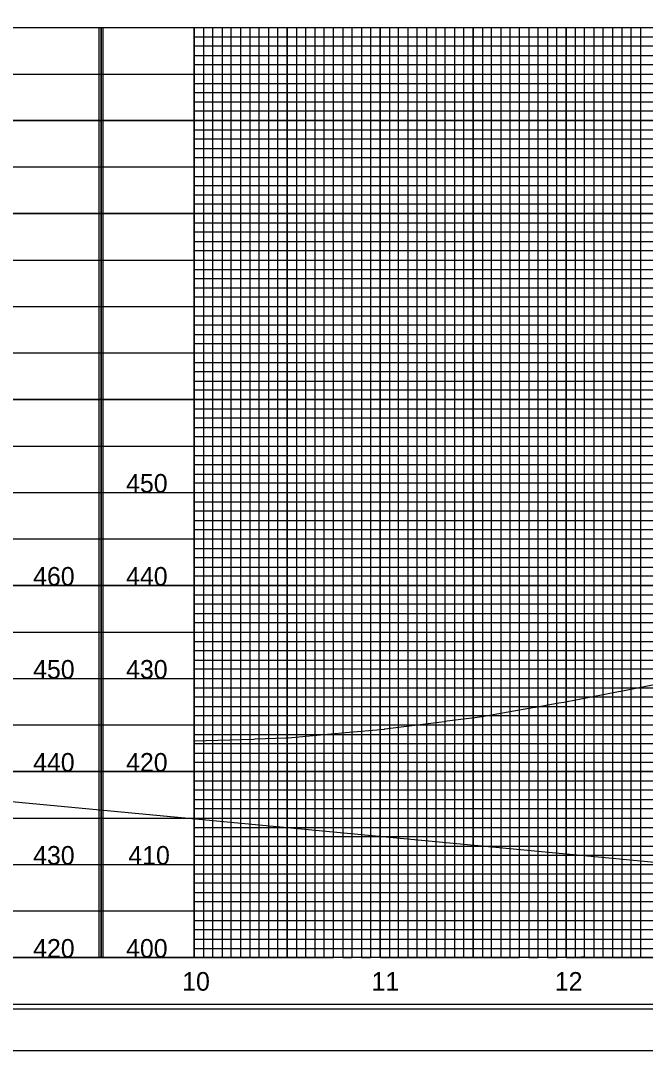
# Model space of a CAD drawing. Extents: x 571503 to 593215, y -77195 to -51828.
# Drawn here: x 586483 to 586818, y -53731 to -53168 of the extents above; entities that cross this region are included whole.
import ezdxf

# ---------------------------------------------------------------- set-up
doc = ezdxf.new("R2010")
doc.units = 0
for name, color, linetype in [('Default', 7, 'Continuous'), ('Exist Vertical Profile Ground Line', 7, 'Continuous'), ('Exist Vertical Profile Horizontal Axis Label Major', 7, 'Continuous'), ('Exist Vertical Profile Vertical Axis Label', 7, 'Continuous'), ('Prop PFL Text', 7, 'Continuous'), ('Prop VPI Label', 7, 'Continuous'), ('Sheet Clip Boundary CELL', 7, 'Continuous'), ('Sheet DOT Grid CELL', 7, 'Continuous'), ('Sheet Plot Border Inside CELL', 7, 'Continuous'), ('Sheet Plot Border Outside CELL', 7, 'Continuous'), ('Sheet Profile CELL', 7, 'Continuous'), ('Sheet Profile Grid Major CELL', 7, 'Continuous'), ('Sheet Profile Grid Middle CELL', 7, 'Continuous'), ('Sheet Profile Grid Minor CELL', 7, 'Continuous')]:
    doc.layers.add(name, color=color, linetype=linetype)

msp = doc.modelspace()

# ---------------------------------------------------------------- linework, layer by layer
at = {"layer": 'Default'}
msp.add_line((586525.93, -53671.12), (586575.93, -53671.12), dxfattribs=at)
at = {"layer": 'Exist Vertical Profile Ground Line'}
msp.add_lwpolyline([(586575.93, -53554.59), (586607.92, -53553.6), (586608.69, -53553.54), (586625.29, -53553), (586626.54, -53552.88), (586657.4, -53550.12), (586678.4, -53548.25), (586678.53, -53548.15), (586678.75, -53548.12), (586707.49, -53544.53), (586710.59, -53544.1), (586712.03, -53543.89), (586725.28, -53542.22), (586726.9, -53542.01), (586730.68, -53541.45), (586759.03, -53536.49), (586759.52, -53536.4), (586772.13, -53534.19), (586774.78, -53533.73), (586804.19, -53528.05), (586805.4, -53527.81), (586825.12, -53523.99)], dxfattribs=at)
at = {"layer": 'Prop PFL Text'}
msp.add_line((571620.66, -52186.29), (592499.52, -54154.87), dxfattribs=at)
at = {"layer": 'Prop VPI Label'}
for p, q in [((586524.93, -53671.12), (586524.93, -53171.12)), ((586526.93, -53671.12), (586526.93, -53171.12))]:
    msp.add_line(p, q, dxfattribs=at)
at = {"layer": 'Sheet Clip Boundary CELL'}
msp.add_lwpolyline([(585975.93, -53171.12), (587375.93, -53171.12), (587375.93, -53671.12), (585975.93, -53671.12)], close=True, dxfattribs=at)
at = {"layer": 'Sheet DOT Grid CELL'}
for p, q in [((585925.93, -53171.12), (587425.82, -53171.12)), ((586525.93, -53671.12), (586525.93, -53171.12)), ((586525.93, -53171.12), (586525.93, -53671.12)), ((586575.93, -53671.12), (586575.93, -53171.12)), ((586575.93, -53171.12), (586575.93, -53671.12)), ((586625.93, -53671.12), (586625.93, -53171.12)), ((586625.93, -53171.12), (586625.93, -53671.12)), ((586675.93, -53671.12), (586675.93, -53171.12)), ((586675.93, -53171.12), (586675.93, -53671.12)), ((586725.93, -53671.12), (586725.93, -53171.12)), ((586725.93, -53171.12), (586725.93, -53671.12)), ((586775.93, -53671.12), (586775.93, -53171.12)), ((586775.93, -53171.12), (586775.93, -53671.12)), ((585925.93, -53221.12), (587425.93, -53221.12)), ((585925.93, -53221.12), (587425.82, -53221.12)), ((585925.93, -53271.12), (587425.93, -53271.12)), ((585925.93, -53271.12), (587425.82, -53271.12)), ((585925.93, -53321.12), (587425.93, -53321.12)), ((585925.93, -53321.12), (587425.82, -53321.12)), ((585925.93, -53371.12), (587425.93, -53371.12)), ((585925.93, -53371.12), (587425.82, -53371.12)), ((585925.93, -53421.12), (587425.93, -53421.12)), ((585925.93, -53421.12), (587425.82, -53421.12)), ((585925.93, -53471.12), (587425.93, -53471.12)), ((585925.93, -53471.12), (587425.82, -53471.12)), ((585925.93, -53521.12), (587425.82, -53521.12)), ((585925.93, -53521.12), (586525.93, -53521.12)), ((585925.93, -53571.12), (587425.82, -53571.12)), ((586575.93, -53571.12), (587425.93, -53571.12)), ((585925.93, -53621.12), (587425.93, -53621.12)), ((585925.93, -53621.12), (587425.82, -53621.12))]:
    msp.add_line(p, q, dxfattribs=at)
at = {"layer": 'Sheet Plot Border Inside CELL'}
msp.add_lwpolyline([(585771.93, -53698.67), (587438.43, -53698.67), (587438.43, -52643.57), (585771.93, -52643.57)], close=True, dxfattribs=at)
at = {"layer": 'Sheet Plot Border Outside CELL'}
msp.add_lwpolyline([(585758.93, -53721.12), (587442.93, -53721.12), (587442.93, -52621.12), (585758.93, -52621.12)], close=True, dxfattribs=at)
at = {"layer": 'Sheet Profile CELL'}
for p, q in [((585925.93, -53171.12), (587425.93, -53171.12)), ((587425.93, -53671.12), (585925.93, -53671.12)), ((585925.93, -53696.12), (587425.93, -53696.12)), ((585758.93, -53721.12), (587442.93, -53721.12))]:
    msp.add_line(p, q, dxfattribs=at)
msp.add_lwpolyline([(587425.93, -52646.12), (585925.93, -52646.12), (585925.93, -53696.12), (587425.93, -53696.12)], close=True, dxfattribs=at)
at = {"layer": 'Sheet Profile Grid Major CELL'}
for p, q in [((586525.93, -53171.12), (586575.93, -53171.12)), ((586625.93, -53171.12), (586675.93, -53171.12)), ((586725.93, -53171.12), (586775.93, -53171.12))]:
    msp.add_line(p, q, dxfattribs=at)
for points in [[(586475.93, -53671.12), (586525.93, -53671.12), (586525.93, -53171.12), (586575.93, -53171.12), (586575.93, -53671.12), (586625.93, -53671.12), (586625.93, -53171.12), (586675.93, -53171.12), (586675.93, -53671.12), (586725.93, -53671.12), (586725.93, -53171.12), (586775.93, -53171.12), (586775.93, -53671.12), (586825.93, -53671.12)], [(587425.93, -53221.12), (585925.93, -53221.12)], [(587425.93, -53271.12), (585925.93, -53271.12), (585925.93, -53321.12), (587425.93, -53321.12)], [(587425.93, -53371.12), (585925.93, -53371.12), (585925.93, -53421.12), (587425.93, -53421.12)], [(587425.93, -53471.12), (585925.93, -53471.12), (585925.93, -53521.12), (587425.93, -53521.12)], [(587425.93, -53571.12), (585925.93, -53571.12), (585925.93, -53571.12), (585925.93, -53621.12), (587425.93, -53621.12)], [(587425.93, -53671.12), (585925.93, -53671.12)]]:
    msp.add_lwpolyline(points, dxfattribs=at)
at = {"layer": 'Sheet Profile Grid Middle CELL'}
for p, q in [((586450.93, -53171.12), (586500.93, -53171.12)), ((586550.93, -53171.12), (586600.93, -53171.12)), ((586600.93, -53171.12), (586600.93, -53671.12)), ((586650.93, -53671.12), (586650.93, -53171.12)), ((586650.93, -53171.12), (586700.93, -53171.12)), ((586700.93, -53171.12), (586700.93, -53671.12)), ((586750.93, -53671.12), (586750.93, -53171.12)), ((586750.93, -53171.12), (586800.93, -53171.12)), ((586800.93, -53171.12), (586800.93, -53671.12)), ((586500.93, -53671.12), (586550.93, -53671.12)), ((586550.93, -53671.12), (586550.93, -53671.12)), ((586600.93, -53671.12), (586650.93, -53671.12)), ((586700.93, -53671.12), (586750.93, -53671.12)), ((586800.93, -53671.12), (586850.93, -53671.12))]:
    msp.add_line(p, q, dxfattribs=at)
for points in [[(585925.93, -53196.12), (587425.93, -53196.12)], [(587375.93, -53246.12), (585925.93, -53246.12), (585925.93, -53296.12), (587425.93, -53296.12)], [(587425.93, -53346.12), (585925.93, -53346.12), (585925.93, -53396.12), (587425.93, -53396.12)], [(587425.93, -53446.12), (585925.93, -53446.12), (585925.93, -53496.12), (587425.93, -53496.12)], [(587425.93, -53546.12), (585925.93, -53546.12), (585925.93, -53596.12), (587425.93, -53596.12)], [(587425.93, -53646.12), (585925.93, -53646.12)]]:
    msp.add_lwpolyline(points, dxfattribs=at)
at = {"layer": 'Sheet Profile Grid Minor CELL'}
for p, q in [((586510.93, -53171.12), (586515.93, -53171.12)), ((586520.93, -53171.12), (586530.93, -53171.12)), ((586535.93, -53171.12), (586540.93, -53171.12)), ((586545.93, -53171.12), (586555.93, -53171.12)), ((586560.93, -53171.12), (586565.93, -53171.12)), ((586570.93, -53171.12), (586580.93, -53171.12)), ((586575.93, -53176.12), (587375.93, -53176.12)), ((586580.93, -53171.12), (586580.93, -53671.12)), ((586585.93, -53671.12), (586585.93, -53171.12)), ((586585.93, -53171.12), (586590.93, -53171.12)), ((586590.93, -53171.12), (586590.93, -53671.12)), ((586595.93, -53671.12), (586595.93, -53171.12)), ((586595.93, -53171.12), (586605.93, -53171.12)), ((586605.93, -53171.12), (586605.93, -53671.12)), ((586610.93, -53671.12), (586610.93, -53171.12)), ((586610.93, -53171.12), (586615.93, -53171.12)), ((586615.93, -53171.12), (586615.93, -53671.12)), ((586620.93, -53671.12), (586620.93, -53171.12)), ((586620.93, -53171.12), (586630.93, -53171.12)), ((586630.93, -53171.12), (586630.93, -53671.12)), ((586635.93, -53671.12), (586635.93, -53171.12)), ((586635.93, -53171.12), (586640.93, -53171.12)), ((586640.93, -53171.12), (586640.93, -53671.12)), ((586645.93, -53671.12), (586645.93, -53171.12)), ((586645.93, -53171.12), (586655.93, -53171.12)), ((586655.93, -53171.12), (586655.93, -53671.12)), ((586660.93, -53671.12), (586660.93, -53171.12)), ((586660.93, -53171.12), (586665.93, -53171.12)), ((586665.93, -53171.12), (586665.93, -53671.12)), ((586670.93, -53671.12), (586670.93, -53171.12)), ((586670.93, -53171.12), (586680.93, -53171.12)), ((586680.93, -53171.12), (586680.93, -53671.12)), ((586685.93, -53671.12), (586685.93, -53171.12)), ((586685.93, -53171.12), (586690.93, -53171.12)), ((586690.93, -53171.12), (586690.93, -53671.12)), ((586695.93, -53671.12), (586695.93, -53171.12)), ((586695.93, -53171.12), (586705.93, -53171.12)), ((586705.93, -53171.12), (586705.93, -53671.12)), ((586710.93, -53671.12), (586710.93, -53171.12)), ((586710.93, -53171.12), (586715.93, -53171.12)), ((586715.93, -53171.12), (586715.93, -53671.12)), ((586720.93, -53671.12), (586720.93, -53171.12)), ((586720.93, -53171.12), (586730.93, -53171.12)), ((586730.93, -53171.12), (586730.93, -53671.12)), ((586735.93, -53671.12), (586735.93, -53171.12)), ((586735.93, -53171.12), (586740.93, -53171.12)), ((586740.93, -53171.12), (586740.93, -53671.12)), ((586745.93, -53671.12), (586745.93, -53171.12)), ((586745.93, -53171.12), (586755.93, -53171.12)), ((586755.93, -53171.12), (586755.93, -53671.12)), ((586760.93, -53671.12), (586760.93, -53171.12)), ((586760.93, -53171.12), (586765.93, -53171.12)), ((586765.93, -53171.12), (586765.93, -53671.12)), ((586770.93, -53671.12), (586770.93, -53171.12)), ((586770.93, -53171.12), (586780.93, -53171.12)), ((586780.93, -53171.12), (586780.93, -53671.12)), ((586785.93, -53671.12), (586785.93, -53171.12)), ((586785.93, -53171.12), (586790.93, -53171.12)), ((586790.93, -53171.12), (586790.93, -53671.12)), ((586795.93, -53671.12), (586795.93, -53171.12)), ((586795.93, -53171.12), (586805.93, -53171.12)), ((586805.93, -53171.12), (586805.93, -53671.12)), ((587375.93, -53181.12), (586575.93, -53181.12)), ((586575.93, -53186.12), (587375.93, -53186.12)), ((587375.93, -53191.12), (586575.93, -53191.12)), ((586575.93, -53201.12), (587375.93, -53201.12)), ((587375.93, -53206.12), (586575.93, -53206.12)), ((586575.93, -53211.12), (587375.93, -53211.12)), ((587375.93, -53216.12), (586575.93, -53216.12)), ((586575.93, -53226.12), (587375.93, -53226.12)), ((587375.93, -53231.12), (586575.93, -53231.12)), ((586575.93, -53236.12), (587375.93, -53236.12)), ((587375.93, -53241.12), (586575.93, -53241.12)), ((586575.93, -53251.12), (587375.93, -53251.12)), ((587375.93, -53256.12), (586575.93, -53256.12)), ((586575.93, -53261.12), (587375.93, -53261.12)), ((587375.93, -53266.12), (586575.93, -53266.12)), ((586575.93, -53276.12), (587375.93, -53276.12)), ((587375.93, -53281.12), (586575.93, -53281.12)), ((586575.93, -53286.12), (587375.93, -53286.12)), ((587375.93, -53291.12), (586575.93, -53291.12)), ((586575.93, -53301.12), (587375.93, -53301.12)), ((587375.93, -53306.12), (586575.93, -53306.12)), ((586575.93, -53311.12), (587375.93, -53311.12)), ((587375.93, -53316.12), (586575.93, -53316.12)), ((586575.93, -53326.12), (587375.93, -53326.12)), ((587375.93, -53331.12), (586575.93, -53331.12)), ((586575.93, -53336.12), (587375.93, -53336.12)), ((587375.93, -53341.12), (586575.93, -53341.12)), ((586575.93, -53351.12), (587375.93, -53351.12)), ((587375.93, -53356.12), (586575.93, -53356.12)), ((586575.93, -53361.12), (587375.93, -53361.12)), ((587375.93, -53366.12), (586575.93, -53366.04)), ((586575.93, -53376.12), (587375.93, -53376.12)), ((587375.93, -53381.12), (586575.93, -53381.12)), ((586575.93, -53386.12), (587375.93, -53386.12)), ((587375.93, -53391.12), (586575.93, -53391.12)), ((586575.93, -53401.12), (587375.93, -53401.12)), ((587375.93, -53406.12), (586575.93, -53406.12)), ((586575.93, -53411.12), (587375.93, -53411.12)), ((587375.93, -53416.12), (586575.93, -53416.12)), ((586575.93, -53426.12), (587375.93, -53426.12)), ((587375.93, -53431.12), (586575.93, -53431.12)), ((586575.93, -53436.12), (587375.93, -53436.12)), ((587375.93, -53441.12), (586575.93, -53441.12)), ((586575.93, -53451.12), (587375.93, -53451.12)), ((587375.93, -53456.12), (586575.93, -53456.12)), ((586575.93, -53461.12), (587375.93, -53461.12)), ((587375.93, -53466.12), (586575.93, -53466.12)), ((586575.93, -53476.12), (587375.93, -53476.12)), ((587375.93, -53481.12), (586575.93, -53481.12)), ((586575.93, -53486.12), (587375.93, -53486.12)), ((587375.93, -53491.12), (586575.93, -53491.12)), ((586575.93, -53501.12), (587375.93, -53501.12)), ((587375.93, -53506.12), (586575.93, -53506.12)), ((586575.93, -53511.12), (587375.93, -53511.12)), ((587375.93, -53516.12), (586575.93, -53516.12)), ((586575.93, -53526.12), (587375.93, -53526.12)), ((587375.93, -53531.12), (586575.93, -53531.12)), ((586575.93, -53536.12), (587375.93, -53536.12)), ((587375.93, -53541.12), (586575.93, -53541.12)), ((586575.93, -53551.12), (587375.93, -53551.12)), ((587375.93, -53556.12), (586575.93, -53556.12)), ((586575.93, -53561.12), (587375.93, -53561.12)), ((587375.93, -53566.12), (586575.93, -53566.12)), ((586575.93, -53576.12), (587375.93, -53576.12)), ((587375.93, -53581.12), (586575.93, -53581.12)), ((586575.93, -53586.12), (587375.93, -53586.12)), ((587375.93, -53591.12), (586575.93, -53591.12)), ((586575.93, -53601.12), (587375.93, -53601.12)), ((587375.93, -53606.12), (586575.93, -53606.12)), ((586575.93, -53611.12), (587375.93, -53611.12)), ((587375.93, -53616.12), (586575.93, -53616.12)), ((586575.93, -53626.12), (587375.93, -53626.12)), ((587375.93, -53631.12), (586575.93, -53631.12)), ((586575.93, -53636.12), (587375.93, -53636.12)), ((587375.93, -53641.12), (586575.93, -53641.12)), ((586575.93, -53651.12), (587375.93, -53651.12)), ((587375.93, -53656.12), (586575.93, -53656.12)), ((586575.93, -53661.12), (587375.93, -53661.12)), ((586575.93, -53666.12), (587375.93, -53666.12)), ((586505.93, -53671.12), (586510.93, -53671.12)), ((586515.93, -53671.12), (586520.93, -53671.12)), ((586530.93, -53671.12), (586535.93, -53671.12)), ((586540.93, -53671.12), (586545.93, -53671.12)), ((586555.93, -53671.12), (586560.93, -53671.12)), ((586565.93, -53671.12), (586570.93, -53671.12)), ((586580.93, -53671.12), (586585.93, -53671.12)), ((586590.93, -53671.12), (586595.93, -53671.12)), ((586605.93, -53671.12), (586610.93, -53671.12)), ((586615.93, -53671.12), (586620.93, -53671.12)), ((586630.93, -53671.12), (586630.93, -53671.12)), ((586630.93, -53671.12), (586635.93, -53671.12)), ((586640.93, -53671.12), (586645.93, -53671.12)), ((586655.93, -53671.12), (586660.93, -53671.12)), ((586665.93, -53671.12), (586670.93, -53671.12)), ((586680.93, -53671.12), (586685.93, -53671.12)), ((586690.93, -53671.12), (586695.93, -53671.12)), ((586705.93, -53671.12), (586710.93, -53671.12)), ((586715.93, -53671.12), (586720.93, -53671.12)), ((586730.93, -53671.12), (586735.93, -53671.12)), ((586740.93, -53671.12), (586745.93, -53671.12)), ((586755.93, -53671.12), (586760.93, -53671.12)), ((586765.93, -53671.12), (586770.93, -53671.12)), ((586780.93, -53671.12), (586785.63, -53670.57)), ((586785.63, -53670.57), (586785.93, -53671.12)), ((586790.93, -53671.12), (586795.93, -53671.12)), ((586805.93, -53671.12), (586810.93, -53671.12))]:
    msp.add_line(p, q, dxfattribs=at)
msp.add_lwpolyline([(586810.93, -53671.12), (586810.93, -53171.12), (586815.93, -53171.12), (586815.93, -53671.12), (586820.93, -53671.12)], dxfattribs=at)

# ---------------------------------------------------------------- texts
at = {"layer": 'Exist Vertical Profile Horizontal Axis Label Major'}
for s, p in [('10', (586569.52, -53688.87)), ('11', (586671.36, -53688.87)), ('12', (586769.9, -53688.87))]:
    msp.add_text(s, height=10, dxfattribs=at).set_placement(p)
at = {"layer": 'Exist Vertical Profile Vertical Axis Label'}
for s, p in [('450', (586539.36, -53421.12)), ('460', (586489.36, -53471.12)), ('440', (586539.36, -53471.12)), ('450', (586489.36, -53521.12)), ('430', (586539.36, -53521.12)), ('440', (586489.36, -53571.12)), ('420', (586539.36, -53571.12)), ('430', (586489.36, -53621.12)), ('410', (586540.56, -53621.12)), ('420', (586489.36, -53671.12)), ('400', (586539.36, -53671.12))]:
    msp.add_text(s, height=10, dxfattribs=at).set_placement(p)

doc.saveas('drawing.dxf')
